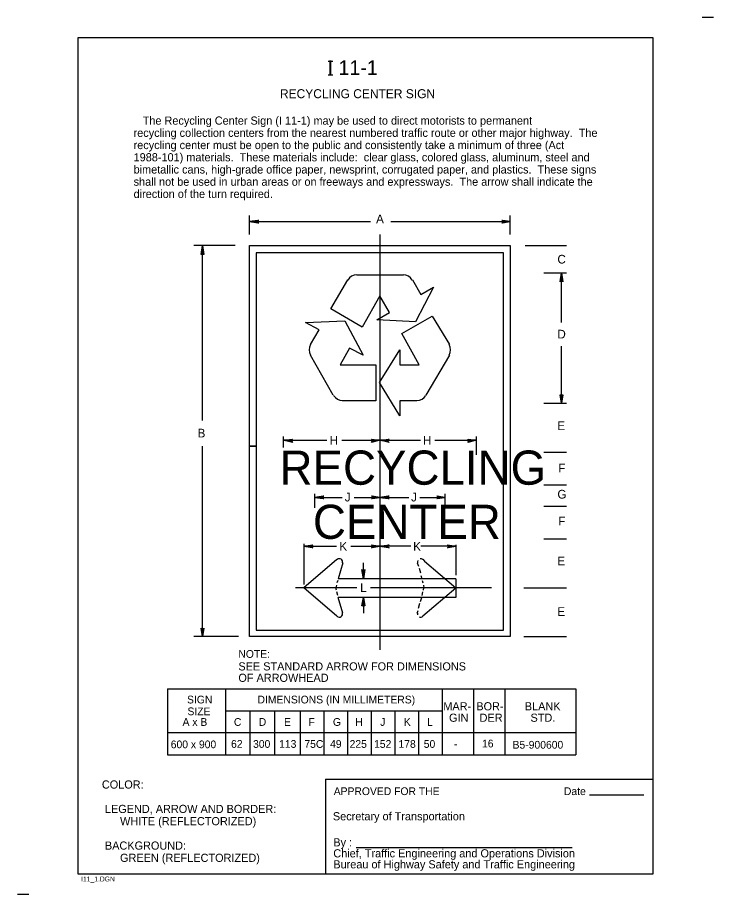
# Model space of a CAD drawing. Extents: x -0.018 to 0.195, y -0.006 to 0.263.
import ezdxf

# ---------------------------------------------------------------- set-up
doc = ezdxf.new("R2010")
doc.units = 0
doc.layers.add('1', color=7, linetype='Continuous')
doc.layers.add('3', color=7, linetype='Continuous')

msp = doc.modelspace()

# ---------------------------------------------------------------- linework, layer by layer
at = {"layer": '1'}
for p, q in [((0.195, 0.26275), (0.1915, 0.26275)), ((0.1765, 0.2565), (0, 0.2565)), ((0, 0.2565), (0, 0)), ((0.1765, 0), (0.1765, 0.2565)), ((0.07675, 0.249375), (0.07825, 0.249375)), ((0.07675, 0.245125), (0.07825, 0.245125)), ((0.052625, 0.196125), (0.052625, 0.202)), ((0.132625, 0.196125), (0.132625, 0.202)), ((0.052625, 0.200125), (0.08975, 0.200125)), ((0.096, 0.200125), (0.132625, 0.200125)), ((0.092625, 0.196125), (0.092625, 0.06875)), ((0.04825, 0.19275), (0.035625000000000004, 0.19275)), ((0.03825, 0.139125), (0.03825, 0.19275)), ((0.052625, 0.13125), (0.052625, 0.19275)), ((0.052625, 0.19275), (0.132625, 0.19275)), ((0.132625, 0.19275), (0.132625, 0.07275)), ((0.13725, 0.19275), (0.149875, 0.19275)), ((0.130625, 0.1905), (0.05475, 0.1905)), ((0.05475, 0.1905), (0.05475, 0.13125)), ((0.130625, 0.07475), (0.130625, 0.1905)), ((0.085625, 0.18375), (0.099875, 0.18375)), ((0.14300000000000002, 0.184375), (0.149875, 0.184375)), ((0.148375, 0.169125), (0.148375, 0.184375)), ((0.077625, 0.173375), (0.082875, 0.18225)), ((0.10262500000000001, 0.18225), (0.10525, 0.17775)), ((0.109125, 0.18), (0.10362500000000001, 0.169375)), ((0.10525, 0.17775), (0.109125, 0.18)), ((0.092625, 0.177375), (0.08725000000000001, 0.16775)), ((0.095625, 0.17225000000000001), (0.092625, 0.177375)), ((0.08725000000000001, 0.16775), (0.077625, 0.173375)), ((0.09175, 0.17), (0.095625, 0.17225000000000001)), ((0.069875, 0.169125), (0.081875, 0.169625)), ((0.081875, 0.169625), (0.08750000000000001, 0.15912500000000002)), ((0.10362500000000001, 0.169375), (0.09175, 0.17)), ((0.099375, 0.16575), (0.10875, 0.171125)), ((0.10875, 0.171125), (0.114, 0.162375)), ((0.074, 0.166875), (0.069875, 0.169125)), ((0.07137500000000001, 0.162375), (0.074, 0.166875)), ((0.10475, 0.156125), (0.099375, 0.16575)), ((0.148375, 0.144375), (0.148375, 0.161875)), ((0.078375, 0.146875), (0.07137500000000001, 0.15912500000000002)), ((0.083375, 0.16125), (0.0805, 0.156125)), ((0.08750000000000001, 0.15912500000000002), (0.083375, 0.16125)), ((0.0925, 0.15075), (0.09875, 0.16075)), ((0.09875, 0.16075), (0.09875, 0.156125)), ((0.114, 0.15912500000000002), (0.10675, 0.146875)), ((0.0805, 0.156125), (0.091375, 0.156125)), ((0.091375, 0.156125), (0.091375, 0.145125)), ((0.09875, 0.156125), (0.10475, 0.156125)), ((0.09875, 0.1405), (0.0925, 0.15075)), ((0.091375, 0.145125), (0.081125, 0.145125)), ((0.10400000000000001, 0.145125), (0.09875, 0.145125)), ((0.09875, 0.145125), (0.09875, 0.1405)), ((0.14300000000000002, 0.144375), (0.149875, 0.144375)), ((0.063, 0.134125), (0.063, 0.13075)), ((0.063, 0.133), (0.076375, 0.133)), ((0.081, 0.133), (0.092625, 0.133)), ((0.092625, 0.133), (0.105125, 0.133)), ((0.1095, 0.133), (0.12225, 0.133)), ((0.12225, 0.134125), (0.12225, 0.1285)), ((0.03825, 0.07275), (0.03825, 0.13125)), ((0.052625, 0.13125), (0.05475, 0.13125)), ((0.05475, 0.13125), (0.052625, 0.13125)), ((0.052625, 0.07275), (0.052625, 0.13125)), ((0.05475, 0.13125), (0.05475, 0.07475)), ((0.14300000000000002, 0.129375), (0.149875, 0.129375)), ((0.14300000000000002, 0.11937500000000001), (0.149875, 0.11937500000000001)), ((0.072625, 0.116625), (0.072625, 0.11225)), ((0.112625, 0.116625), (0.112625, 0.11225)), ((0.072625, 0.1155), (0.081125, 0.1155)), ((0.08475, 0.1155), (0.092625, 0.1155)), ((0.092625, 0.1155), (0.1015, 0.1155)), ((0.104875, 0.1155), (0.112625, 0.1155)), ((0.14300000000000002, 0.11275), (0.149875, 0.11275)), ((0.14300000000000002, 0.10275000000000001), (0.149875, 0.10275000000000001)), ((0.069375, 0.10125), (0.069375, 0.08875)), ((0.069375, 0.1005), (0.079375, 0.1005)), ((0.08375, 0.1005), (0.092625, 0.1005)), ((0.10212500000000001, 0.1005), (0.092625, 0.1005)), ((0.116, 0.1005), (0.10525, 0.1005)), ((0.116, 0.100875), (0.116, 0.091625)), ((0.0795, 0.096375), (0.069375, 0.08775000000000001)), ((0.08125, 0.095375), (0.079875, 0.0905)), ((0.08762500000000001, 0.0905), (0.08762500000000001, 0.095375)), ((0.104125, 0.095375), (0.1045, 0.094375)), ((0.105875, 0.0965), (0.106375, 0.095875)), ((0.106375, 0.095875), (0.116, 0.08775000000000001)), ((0.10475, 0.09375), (0.105125, 0.092375)), ((0.07975, 0.09), (0.0795, 0.08925)), ((0.116, 0.0905), (0.079875, 0.0905)), ((0.10525, 0.0915), (0.1055, 0.0905)), ((0.105625, 0.09), (0.105875, 0.08925)), ((0.116, 0.0905), (0.116, 0.08475)), ((0.085625, 0.08775000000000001), (0.06675, 0.08775000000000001)), ((0.0795, 0.079), (0.069375, 0.08775000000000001)), ((0.079375, 0.0885), (0.079125, 0.08775000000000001)), ((0.079375, 0.08700000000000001), (0.079125, 0.08775000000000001)), ((0.07975, 0.085375), (0.0795, 0.08650000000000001)), ((0.12687500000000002, 0.08775000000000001), (0.08975, 0.08775000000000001)), ((0.105625, 0.085375), (0.105875, 0.08650000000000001)), ((0.105875, 0.079125), (0.116, 0.08775000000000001)), ((0.106, 0.0885), (0.106125, 0.08775000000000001)), ((0.106, 0.08700000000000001), (0.106125, 0.08775000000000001)), ((0.136875, 0.08775000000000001), (0.149875, 0.08775000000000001)), ((0.08125, 0.08), (0.079875, 0.08475)), ((0.116, 0.08475), (0.079875, 0.08475)), ((0.08762500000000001, 0.08475), (0.08762500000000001, 0.08)), ((0.105125, 0.0835), (0.1055, 0.08475)), ((0.104125, 0.08), (0.104375, 0.08075)), ((0.1045, 0.0815), (0.104875, 0.083)), ((0.04925, 0.07275), (0.035625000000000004, 0.07275)), ((0.132625, 0.07275), (0.052625, 0.07275)), ((0.05475, 0.07475), (0.130625, 0.07475)), ((0.136875, 0.07275), (0.149875, 0.07275)), ((0.076, 0.029), (0.1765, 0.029)), ((0.076, 0.029), (0.076, 0)), ((0.157, 0.02425), (0.173625, 0.02425)), ((0.085375, 0.008), (0.151625, 0.008)), ((0, 0), (0.1765, 0)), ((-0.015, -0.0063750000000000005), (-0.0185, -0.0063750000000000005))]:
    msp.add_line(p, q, dxfattribs=at)
for points in [[(0.05525, 0.19975), (0.055125, 0.2), (0.052625, 0.200125), (0.05525, 0.19975), (0.0555, 0.19975), (0.052625, 0.200125), (0.055125, 0.200375), (0.05525, 0.2005), (0.052625, 0.200125), (0.0555, 0.2005), (0.05525, 0.2005)], [(0.13025, 0.2005), (0.13025, 0.200375), (0.132625, 0.200125), (0.13025, 0.2005), (0.130125, 0.2005), (0.132625, 0.200125), (0.13025, 0.2), (0.13025, 0.19975), (0.132625, 0.200125), (0.130125, 0.19975), (0.13025, 0.19975)], [(0.037875, 0.19012500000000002), (0.038, 0.19012500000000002), (0.03825, 0.19275), (0.037875, 0.19012500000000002), (0.037875, 0.19), (0.03825, 0.19275), (0.038375, 0.19012500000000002), (0.038625, 0.19012500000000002), (0.03825, 0.19275), (0.038625, 0.19), (0.038625, 0.19012500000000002)], [(0.148, 0.181875), (0.14825, 0.181875), (0.148375, 0.184375), (0.148, 0.181875), (0.148, 0.181625), (0.148375, 0.184375), (0.148625, 0.181875), (0.14875, 0.181875), (0.148375, 0.184375), (0.14875, 0.181625), (0.14875, 0.181875)], [(0.14875, 0.146875), (0.148625, 0.146875), (0.148375, 0.144375), (0.14875, 0.146875), (0.14875, 0.147), (0.148375, 0.144375), (0.14825, 0.146875), (0.148, 0.146875), (0.148375, 0.144375), (0.148, 0.147), (0.148, 0.146875)], [(0.065625, 0.132625), (0.065625, 0.13275), (0.063, 0.133), (0.065625, 0.132625), (0.065875, 0.132375), (0.063, 0.133), (0.065625, 0.133), (0.065625, 0.133125), (0.063, 0.133), (0.065875, 0.133375), (0.065625, 0.133125)], [(0.09025, 0.133125), (0.09025, 0.133), (0.092625, 0.133), (0.09025, 0.133125), (0.090125, 0.133375), (0.092625, 0.133), (0.09025, 0.13275), (0.09025, 0.132625), (0.092625, 0.133), (0.090125, 0.132375), (0.09025, 0.132625)], [(0.09525, 0.132625), (0.095125, 0.13275), (0.092625, 0.133), (0.09525, 0.132625), (0.0955, 0.132375), (0.092625, 0.133), (0.095125, 0.133), (0.09525, 0.133125), (0.092625, 0.133), (0.0955, 0.133375), (0.09525, 0.133125)], [(0.11975000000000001, 0.133125), (0.11987500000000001, 0.133), (0.12225, 0.133), (0.11975000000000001, 0.133125), (0.11975000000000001, 0.133375), (0.12225, 0.133), (0.11987500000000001, 0.13275), (0.11975000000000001, 0.132625), (0.12225, 0.133), (0.11975000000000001, 0.132375), (0.11975000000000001, 0.132625)], [(0.07525, 0.115125), (0.075125, 0.115375), (0.072625, 0.1155), (0.07525, 0.115125), (0.0755, 0.115125), (0.072625, 0.1155), (0.075125, 0.11575), (0.07525, 0.115875), (0.072625, 0.1155), (0.0755, 0.115875), (0.07525, 0.115875)], [(0.09025, 0.115875), (0.09025, 0.11575), (0.092625, 0.1155), (0.09025, 0.115875), (0.090125, 0.115875), (0.092625, 0.1155), (0.09025, 0.115375), (0.09025, 0.115125), (0.092625, 0.1155), (0.090125, 0.115125), (0.09025, 0.115125)], [(0.09525, 0.115125), (0.095125, 0.115375), (0.092625, 0.1155), (0.09525, 0.115125), (0.0955, 0.115125), (0.092625, 0.1155), (0.095125, 0.11575), (0.09525, 0.115875), (0.092625, 0.1155), (0.0955, 0.115875), (0.09525, 0.115875)], [(0.11025, 0.115875), (0.11025, 0.11575), (0.112625, 0.1155), (0.11025, 0.115875), (0.110125, 0.115875), (0.112625, 0.1155), (0.11025, 0.115375), (0.11025, 0.115125), (0.112625, 0.1155), (0.110125, 0.115125), (0.11025, 0.115125)], [(0.07187500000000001, 0.100125), (0.07175000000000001, 0.100375), (0.069375, 0.1005), (0.07187500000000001, 0.100125), (0.072125, 0.1), (0.069375, 0.1005), (0.07175000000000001, 0.1005), (0.07187500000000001, 0.10075), (0.069375, 0.1005), (0.072125, 0.100875), (0.07187500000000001, 0.10075)], [(0.09025, 0.10075), (0.09025, 0.1005), (0.092625, 0.1005), (0.09025, 0.10075), (0.090125, 0.100875), (0.092625, 0.1005), (0.09025, 0.100375), (0.09025, 0.100125), (0.092625, 0.1005), (0.090125, 0.1), (0.09025, 0.100125)], [(0.09525, 0.100125), (0.095125, 0.100375), (0.092625, 0.1005), (0.09525, 0.100125), (0.0955, 0.1), (0.092625, 0.1005), (0.095125, 0.1005), (0.09525, 0.10075), (0.092625, 0.1005), (0.0955, 0.100875), (0.09525, 0.10075)], [(0.113625, 0.10075), (0.113625, 0.1005), (0.116, 0.1005), (0.113625, 0.10075), (0.113375, 0.100875), (0.116, 0.1005), (0.113625, 0.100375), (0.113625, 0.100125), (0.116, 0.1005), (0.113375, 0.1), (0.113625, 0.100125)], [(0.088, 0.093125), (0.08787500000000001, 0.093125), (0.08762500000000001, 0.0905), (0.088, 0.093125), (0.088, 0.093375), (0.08762500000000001, 0.0905), (0.08750000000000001, 0.093125), (0.08725000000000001, 0.093125), (0.08762500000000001, 0.0905), (0.08712500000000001, 0.093375), (0.08725000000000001, 0.093125)], [(0.08725000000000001, 0.08225), (0.08750000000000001, 0.082375), (0.08762500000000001, 0.08475), (0.08725000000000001, 0.08225), (0.08712500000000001, 0.08225), (0.08762500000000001, 0.08475), (0.08762500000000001, 0.082375), (0.08787500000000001, 0.08225), (0.08762500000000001, 0.08475), (0.088, 0.08225), (0.08787500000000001, 0.08225)], [(0.038625, 0.075125), (0.038375, 0.075125), (0.03825, 0.07275), (0.038625, 0.075125), (0.038625, 0.075375), (0.03825, 0.07275), (0.03825, 0.075125), (0.038, 0.075125), (0.03825, 0.07275), (0.037875, 0.075375), (0.038, 0.075125)]]:
    msp.add_lwpolyline(points, dxfattribs=at)
for centre, radius, start, end in [((0.08556806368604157, 0.1805804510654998), 0.0032039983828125, 90.00000000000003, 149.9988666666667), ((0.09983765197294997, 0.1805804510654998), 0.0032039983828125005, 29.998961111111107, 90), ((0.07412268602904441, 0.16075546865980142), 0.0032039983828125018, 149.99896111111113, 210.00000000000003), ((0.11113389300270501, 0.16075387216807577), 0.0032039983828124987, 330, 29.99886666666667), ((0.08125748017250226, 0.14839764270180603), 0.0032039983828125, 210.00000000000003, 269.9988666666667), ((0.10399909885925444, 0.14839604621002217), 0.0032039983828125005, 269.99896111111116, 330.00000000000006), ((0.0802026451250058, 0.09561803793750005), 0.0010416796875, 345.0676583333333, 130.6957638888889), ((0.10520295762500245, 0.09561803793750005), 0.0010416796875, 149.73224722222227, 194.93234166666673), ((0.10520295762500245, 0.09561803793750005), 0.0010416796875, 49.304236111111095, 102.74835555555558), ((0.0802026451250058, 0.07978450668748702), 0.0010416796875, 229.30423611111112, 14.93234166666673), ((0.10520295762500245, 0.07978450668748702), 0.0010416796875, 165.06765833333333, 197.2154361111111), ((0.10520295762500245, 0.07978450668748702), 0.0010416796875, 243.42871388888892, 310.6957638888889)]:
    msp.add_arc(centre, radius, start, end, dxfattribs=at)
at = {"layer": '3'}
for p, q in [((0.0275, 0.05675), (0.15275, 0.05675)), ((0.0275, 0.05675), (0.0275, 0.0365)), ((0.04525, 0.05675), (0.04525, 0.0365)), ((0.11175, 0.05675), (0.11175, 0.0365)), ((0.121375, 0.05675), (0.121375, 0.0365)), ((0.131, 0.05675), (0.131, 0.0365)), ((0.15275, 0.05675), (0.15275, 0.0365)), ((0.11175, 0.049875), (0.04525, 0.049875)), ((0.05275, 0.049875), (0.05275, 0.0365)), ((0.060375, 0.049875), (0.060375, 0.0365)), ((0.06825, 0.049875), (0.06825, 0.0365)), ((0.0755, 0.049875), (0.0755, 0.0365)), ((0.08275, 0.049875), (0.08275, 0.0365)), ((0.09, 0.049875), (0.09, 0.0365)), ((0.09725, 0.049875), (0.09725, 0.0365)), ((0.1045, 0.049875), (0.1045, 0.0365)), ((0.0275, 0.043375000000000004), (0.15275, 0.043375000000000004)), ((0.0275, 0.0365), (0.15275, 0.0365))]:
    msp.add_line(p, q, dxfattribs=at)

# ---------------------------------------------------------------- texts
at = {"layer": '1'}
for s, height, p in [('I 11-1', 0.0045000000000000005, (0.076625, 0.245125)), ('RECYCLING CENTER SIGN', 0.00275025, (0.062, 0.23800000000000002)), ('A', 0.0026632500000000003, (0.0915, 0.199625)), ('C', 0.0026632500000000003, (0.147125, 0.18725)), ('D', 0.0026632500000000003, (0.147125, 0.16425)), ('E', 0.0026632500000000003, (0.147125, 0.136125)), ('B', 0.0026632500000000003, (0.03675, 0.133875)), ('H', 0.0026632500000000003, (0.07725, 0.131625)), ('H', 0.0026632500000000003, (0.105875, 0.131625)), ('RECYCLING', 0.010485, (0.061875, 0.11937500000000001)), ('F', 0.0026632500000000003, (0.147375, 0.123125)), ('J', 0.0026632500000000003, (0.081875, 0.11425)), ('J', 0.0026632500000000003, (0.10225000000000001, 0.11425)), ('G', 0.0026632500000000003, (0.147125, 0.115125)), ('CENTER', 0.010485, (0.072125, 0.10275000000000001)), ('F', 0.0026632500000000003, (0.147375, 0.106875)), ('K', 0.0026632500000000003, (0.08025, 0.099125)), ('K', 0.0026632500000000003, (0.10287500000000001, 0.099125)), ('E', 0.0026632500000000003, (0.147125, 0.094625)), ('L', 0.002625, (0.08662500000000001, 0.08650000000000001)), ('E', 0.0026632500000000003, (0.147125, 0.079125)), ('NOTE:', 0.0023752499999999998, (0.04925, 0.06625)), ('SEE STANDARD ARROW FOR DIMENSIONS', 0.0024997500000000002, (0.04925, 0.062375)), ('OF ARROWHEAD', 0.0024997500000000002, (0.04925, 0.058875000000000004)), ('COLOR:', 0.0024997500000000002, (0.0073750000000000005, 0.026125)), ('APPROVED FOR THE', 0.0023752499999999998, (0.0785, 0.024125)), ('Date ', 0.0023752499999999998, (0.149125, 0.024125)), (' LEGEND, ARROW AND BORDER:', 0.0024997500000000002, (0.0073750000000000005, 0.018625)), ('Secretary of Transportation', 0.0024997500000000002, (0.07825, 0.016375)), ('      WHITE (REFLECTORIZED)', 0.0024997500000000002, (0.0073750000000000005, 0.014875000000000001)), ('By :', 0.0024997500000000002, (0.078375, 0.008375)), (' BACKGROUND:', 0.0024997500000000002, (0.0073750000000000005, 0.0073750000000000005)), ('      GREEN (REFLECTORIZED)', 0.0024997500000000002, (0.0073750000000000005, 0.003625)), ('Chief, Traffic Engineering and Operations Division', 0.0024997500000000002, (0.078375, 0.005)), ('Bureau of Highway Safety and Traffic Engineering', 0.0024997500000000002, (0.078375, 0.0016250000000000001)), ('I11_1.DGN', 0.0015, (0.001, -0.002375))]:
    msp.add_text(s, height=height, dxfattribs=at).set_placement(p)
at = {"layer": '3'}
for s, height, p in [('     The Recycling Center Sign (I 11-1) may be used to direct motorists to permanent', 0.0024997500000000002, (0.01525, 0.229875)), ('  recycling collection centers from the nearest numbered traffic route or other major highway.  The', 0.0024997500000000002, (0.01525, 0.226125)), ('  recycling center must be open to the public and consistently take a minimum of three (Act ', 0.0024997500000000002, (0.01525, 0.22237500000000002)), ('  1988-101) materials.  These materials include:  clear glass, colored glass, aluminum, steel and', 0.0024997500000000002, (0.01525, 0.218625)), ('  bimetallic cans, high-grade office paper, newsprint, corrugated paper, and plastics.  These signs', 0.0024997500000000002, (0.01525, 0.214875)), ('  shall not be used in urban areas or on freeways and expressways.  The arrow shall indicate the', 0.0024997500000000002, (0.01525, 0.211125)), ('  direction of the turn required. ', 0.0024997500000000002, (0.01525, 0.207375)), ('SIGN', 0.0023752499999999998, (0.0335, 0.05225)), ('DIMENSIONS (IN MILLIMETERS)', 0.0023752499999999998, (0.055125, 0.05225)), ('MAR-', 0.0024997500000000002, (0.112125, 0.050125)), ('BOR-', 0.0024997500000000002, (0.12225, 0.050125)), ('BLANK', 0.0024997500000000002, (0.137125, 0.050125)), ('SIZE', 0.0023752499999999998, (0.033625, 0.048625)), ('GIN', 0.0024997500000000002, (0.113875, 0.046625)), ('DER', 0.0024997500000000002, (0.12325, 0.046625)), ('STD.', 0.0024997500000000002, (0.138875, 0.046625)), ('A x B', 0.0023752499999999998, (0.032125, 0.045375)), ('C', 0.0023752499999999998, (0.047875, 0.045375)), ('D', 0.0023752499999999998, (0.0555, 0.045375)), ('E', 0.0023752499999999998, (0.06325, 0.045375)), ('F', 0.0023752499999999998, (0.07075000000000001, 0.045375)), ('G', 0.0023752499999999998, (0.07825, 0.045375)), ('H', 0.0023752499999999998, (0.085125, 0.045375)), ('J', 0.0023752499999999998, (0.09275, 0.045375)), ('K', 0.0023752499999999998, (0.1, 0.045375)), ('L', 0.0023752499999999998, (0.107125, 0.045375)), ('600 x 900', 0.0023752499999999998, (0.0285, 0.0385)), ('62', 0.0023752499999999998, (0.047, 0.038625)), ('300', 0.0023752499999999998, (0.05375, 0.038625)), ('113', 0.0023752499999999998, (0.06175, 0.038625)), ('75C', 0.0023752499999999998, (0.0695, 0.038625)), ('49', 0.0023752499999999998, (0.077375, 0.038625)), ('225', 0.0023752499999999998, (0.083375, 0.038625)), ('152', 0.0023752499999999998, (0.090875, 0.038625)), ('178', 0.0023752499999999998, (0.098375, 0.038625)), ('50', 0.0023752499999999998, (0.106125, 0.038625)), ('16', 0.0023752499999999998, (0.124, 0.03875)), ('B5-900600', 0.0023752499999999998, (0.133375, 0.038375)), ('-', 0.0023752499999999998, (0.115375, 0.038625))]:
    msp.add_text(s, height=height, dxfattribs=at).set_placement(p)

doc.saveas('drawing.dxf')
